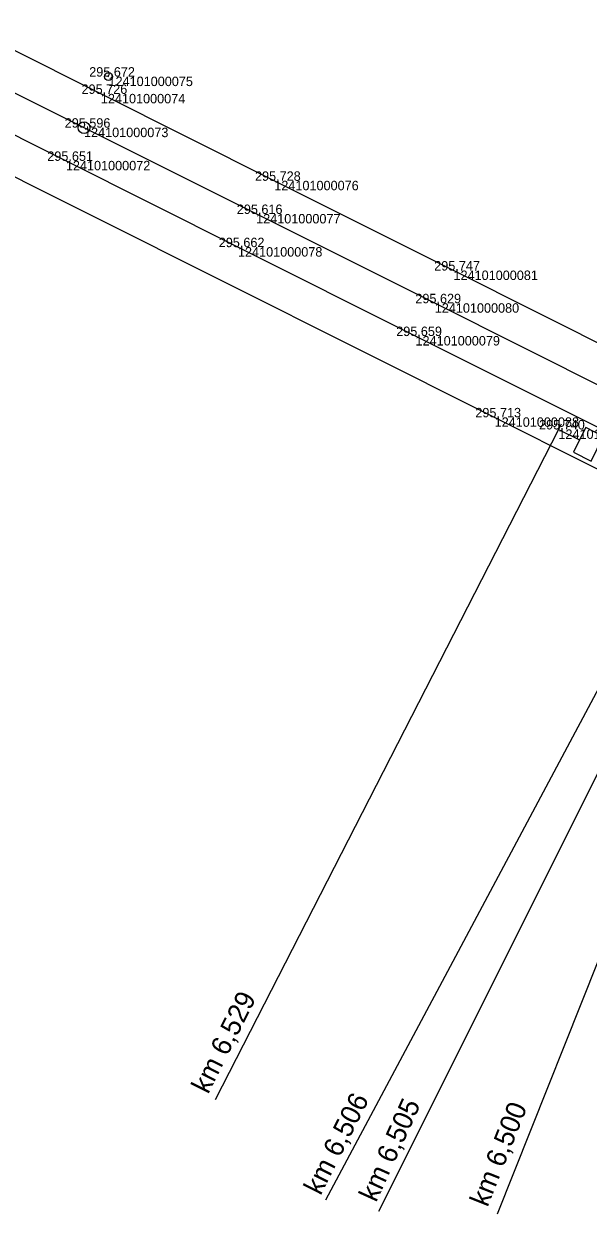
# Model space of a CAD drawing. Extents: x -616949 to -607976, y -1164436 to -1159224.
# Drawn here: x -612978.5 to -612906.9, y -1161793.6 to -1161642.5 of the extents above; entities that cross this region are included whole.
import ezdxf

# ---------------------------------------------------------------- set-up
doc = ezdxf.new("R2010")
doc.units = 0
for name, color, linetype in [('Vrstva 1', 7, 'Continuous'), ('Vrstva 3', 7, 'Continuous'), ('Vrstva 60', 7, 'Continuous'), ('Vrstva 61', 7, 'Continuous'), ('Vrstva 7', 7, 'Continuous')]:
    doc.layers.add(name, color=color, linetype=linetype)

msp = doc.modelspace()

# ---------------------------------------------------------------- linework, layer by layer
at = {"layer": 'Vrstva 1'}
for points in [[(-612836.3, -1161723.7), (-612837.64, -1161723.01), (-612851, -1161716.12), (-612864.8, -1161706.96), (-612874.11, -1161700.74), (-612883.8, -1161694.67), (-612893.99, -1161688.92), (-612900.94, -1161685.35), (-612902.32, -1161684.67), (-612923.96, -1161673.82), (-612946.7, -1161662.43), (-612968.71, -1161651.4), (-612992.18, -1161639.63), (-613014.55, -1161628.42), (-613038.93, -1161616.22), (-613057.44, -1161606.93), (-613076.92, -1161597.16), (-613100.26, -1161585.47), (-613122.66, -1161574.25), (-613146.78, -1161562.2), (-613166.98, -1161552.11), (-613189.63, -1161540.79)], [(-612836.3, -1161723.7), (-612837.64, -1161723.01), (-612851, -1161716.12), (-612865.7, -1161708.54), (-612879.87, -1161701.29), (-612896.11, -1161693.08), (-612897.16, -1161692.56), (-612899.6, -1161691.36), (-612902.62, -1161689.84), (-612904.01, -1161689.16), (-612926.34, -1161677.97), (-612949.01, -1161666.64), (-612970.85, -1161655.69), (-612994.2, -1161644.02), (-613016.8, -1161632.71), (-613041.11, -1161620.53), (-613059.39, -1161611.38), (-613079.39, -1161601.37), (-613102.4, -1161589.86), (-613124.84, -1161578.63), (-613149.33, -1161566.38), (-613169.01, -1161556.54), (-613191.83, -1161545.12)], [(-612838.4, -1161727.97), (-612839.52, -1161727.39), (-612849.62, -1161722.19), (-612861.87, -1161715.89), (-612876.82, -1161708.21), (-612890.37, -1161701.36), (-612894.8, -1161699.12), (-612896.29, -1161698.37), (-612899.37, -1161696.83), (-612901.81, -1161695.62), (-612928.78, -1161682.13), (-612951.31, -1161670.85), (-612973.15, -1161659.9), (-612996.39, -1161648.28), (-613019.15, -1161636.88), (-613042.98, -1161624.98), (-613061.36, -1161615.73), (-613081.95, -1161605.44), (-613104.41, -1161594.19), (-613127.64, -1161582.55), (-613152.33, -1161570.2), (-613170.83, -1161560.95), (-613193.86, -1161549.42)], [(-612838.4, -1161727.97), (-612839.52, -1161727.39), (-612849.62, -1161722.19), (-612862.62, -1161717.56), (-612874.04, -1161713.43), (-612884.82, -1161709.14), (-612890.21, -1161706.69), (-612892.64, -1161705.54), (-612895.15, -1161704.3), (-612918.74, -1161692.45), (-613021.43, -1161641.02), (-613045.3, -1161629.07), (-613063.44, -1161619.97), (-613084.1, -1161609.63), (-613106.49, -1161598.41), (-613129.98, -1161586.61), (-613154.55, -1161574.23)]]:
    msp.add_lwpolyline(points, dxfattribs=at)
at = {"layer": 'Vrstva 3'}
for p, q in [((-612893.9, -1161704.92), (-612940.21, -1161791.8)), ((-612890.21, -1161706.69), (-612933.49, -1161793.23)), ((-612884.82, -1161709.14), (-612918.42, -1161793.57))]:
    msp.add_line(p, q, dxfattribs=at)
at = {"layer": 'Vrstva 60'}
for p, q in [((-612967.74, -1161649.21), (-612967.74, -1161649.21)), ((-612968.71, -1161651.4), (-612968.71, -1161651.4)), ((-612970.85, -1161655.69), (-612970.85, -1161655.69)), ((-612973.15, -1161659.9), (-612973.15, -1161659.9)), ((-612946.7, -1161662.43), (-612946.7, -1161662.43)), ((-612949.01, -1161666.64), (-612949.01, -1161666.64)), ((-612951.31, -1161670.85), (-612951.31, -1161670.85)), ((-612923.96, -1161673.82), (-612923.96, -1161673.82)), ((-612926.34, -1161677.97), (-612926.34, -1161677.97)), ((-612928.78, -1161682.13), (-612928.78, -1161682.13)), ((-612918.74, -1161692.45), (-612918.74, -1161692.45)), ((-612910.65, -1161693.98), (-612910.65, -1161693.98))]:
    msp.add_line(p, q, dxfattribs=at)
at = {"layer": 'Vrstva 7'}
for p, q in [((-612967.7, -1161649.23), (-612967.79, -1161649.18)), ((-612910.31, -1161693.31), (-612910.99, -1161694.65)), ((-612910.65, -1161693.98), (-612954.21, -1161779.05))]:
    msp.add_line(p, q, dxfattribs=at)
msp.add_lwpolyline([(-612910.65, -1161693.98), (-612907.97, -1161695.32), (-612908.75, -1161696.88), (-612906.51, -1161698), (-612904.95, -1161694.87), (-612907.18, -1161693.75), (-612907.97, -1161695.32)], dxfattribs=at)
for centre, radius in [((-612967.74, -1161649.21), 0.5), ((-612970.85, -1161655.69), 0.75)]:
    msp.add_circle(centre, radius, dxfattribs=at)

# ---------------------------------------------------------------- texts
at = {"layer": 'Vrstva 3'}
for s, rotation, p in [('km 6,506', 63.1851, (-612940.84, -1161791.28)), ('km 6,505', 65.5993, (-612933.78, -1161792.16)), ('km 6,500', 68.3031, (-612919.65, -1161792.76))]:
    msp.add_text(s, height=2.5, rotation=rotation, dxfattribs=at).set_placement(p)
at = {"layer": 'Vrstva 60'}
for s, p in [('124101000075', (-612967.74, -1161650.41)), ('124101000074', (-612968.71, -1161652.6)), ('124101000073', (-612970.85, -1161656.89)), ('124101000072', (-612973.15, -1161661.1)), ('124101000076', (-612946.7, -1161663.63)), ('124101000077', (-612949.01, -1161667.84)), ('124101000078', (-612951.31, -1161672.05)), ('124101000081', (-612923.96, -1161675.02)), ('124101000080', (-612926.34, -1161679.17)), ('124101000079', (-612928.78, -1161683.33)), ('124101000088', (-612918.74, -1161693.65)), ('124101000087', (-612910.65, -1161695.18))]:
    msp.add_text(s, height=1.2, dxfattribs=at).set_placement(p)
at = {"layer": 'Vrstva 61'}
for s, p in [('295.672', (-612970.19, -1161649.21)), ('295.726', (-612971.16, -1161651.4)), ('295.596', (-612973.3, -1161655.69)), ('295.651', (-612975.51, -1161659.9)), ('295.728', (-612949.15, -1161662.43)), ('295.616', (-612951.46, -1161666.64)), ('295.662', (-612953.75, -1161670.85)), ('295.747', (-612926.41, -1161673.82)), ('295.629', (-612928.8, -1161677.97)), ('295.659', (-612931.23, -1161682.13)), ('295.713', (-612921.19, -1161692.45)), ('295.740', (-612913.1, -1161693.98))]:
    msp.add_text(s, height=1.2, dxfattribs=at).set_placement(p)
at = {"layer": 'Vrstva 7'}
msp.add_text('km 6,529', height=2.5, rotation=63.4324, dxfattribs=at).set_placement((-612955.1, -1161778.42))

doc.saveas('drawing.dxf')
